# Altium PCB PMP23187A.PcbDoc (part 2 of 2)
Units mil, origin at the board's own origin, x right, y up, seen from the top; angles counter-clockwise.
Board outline 4000 x 3500 mil, 6 copper layers (Top Layer, Signal Layer 1, Signal Layer 2, Signal Layer 3, Signal Layer 4, Bottom Layer), stack 61.8 mil thick; 121 components, 42 nets, 273 pads, 535 vias.
Unrouted connection lines stored in the file: 23.
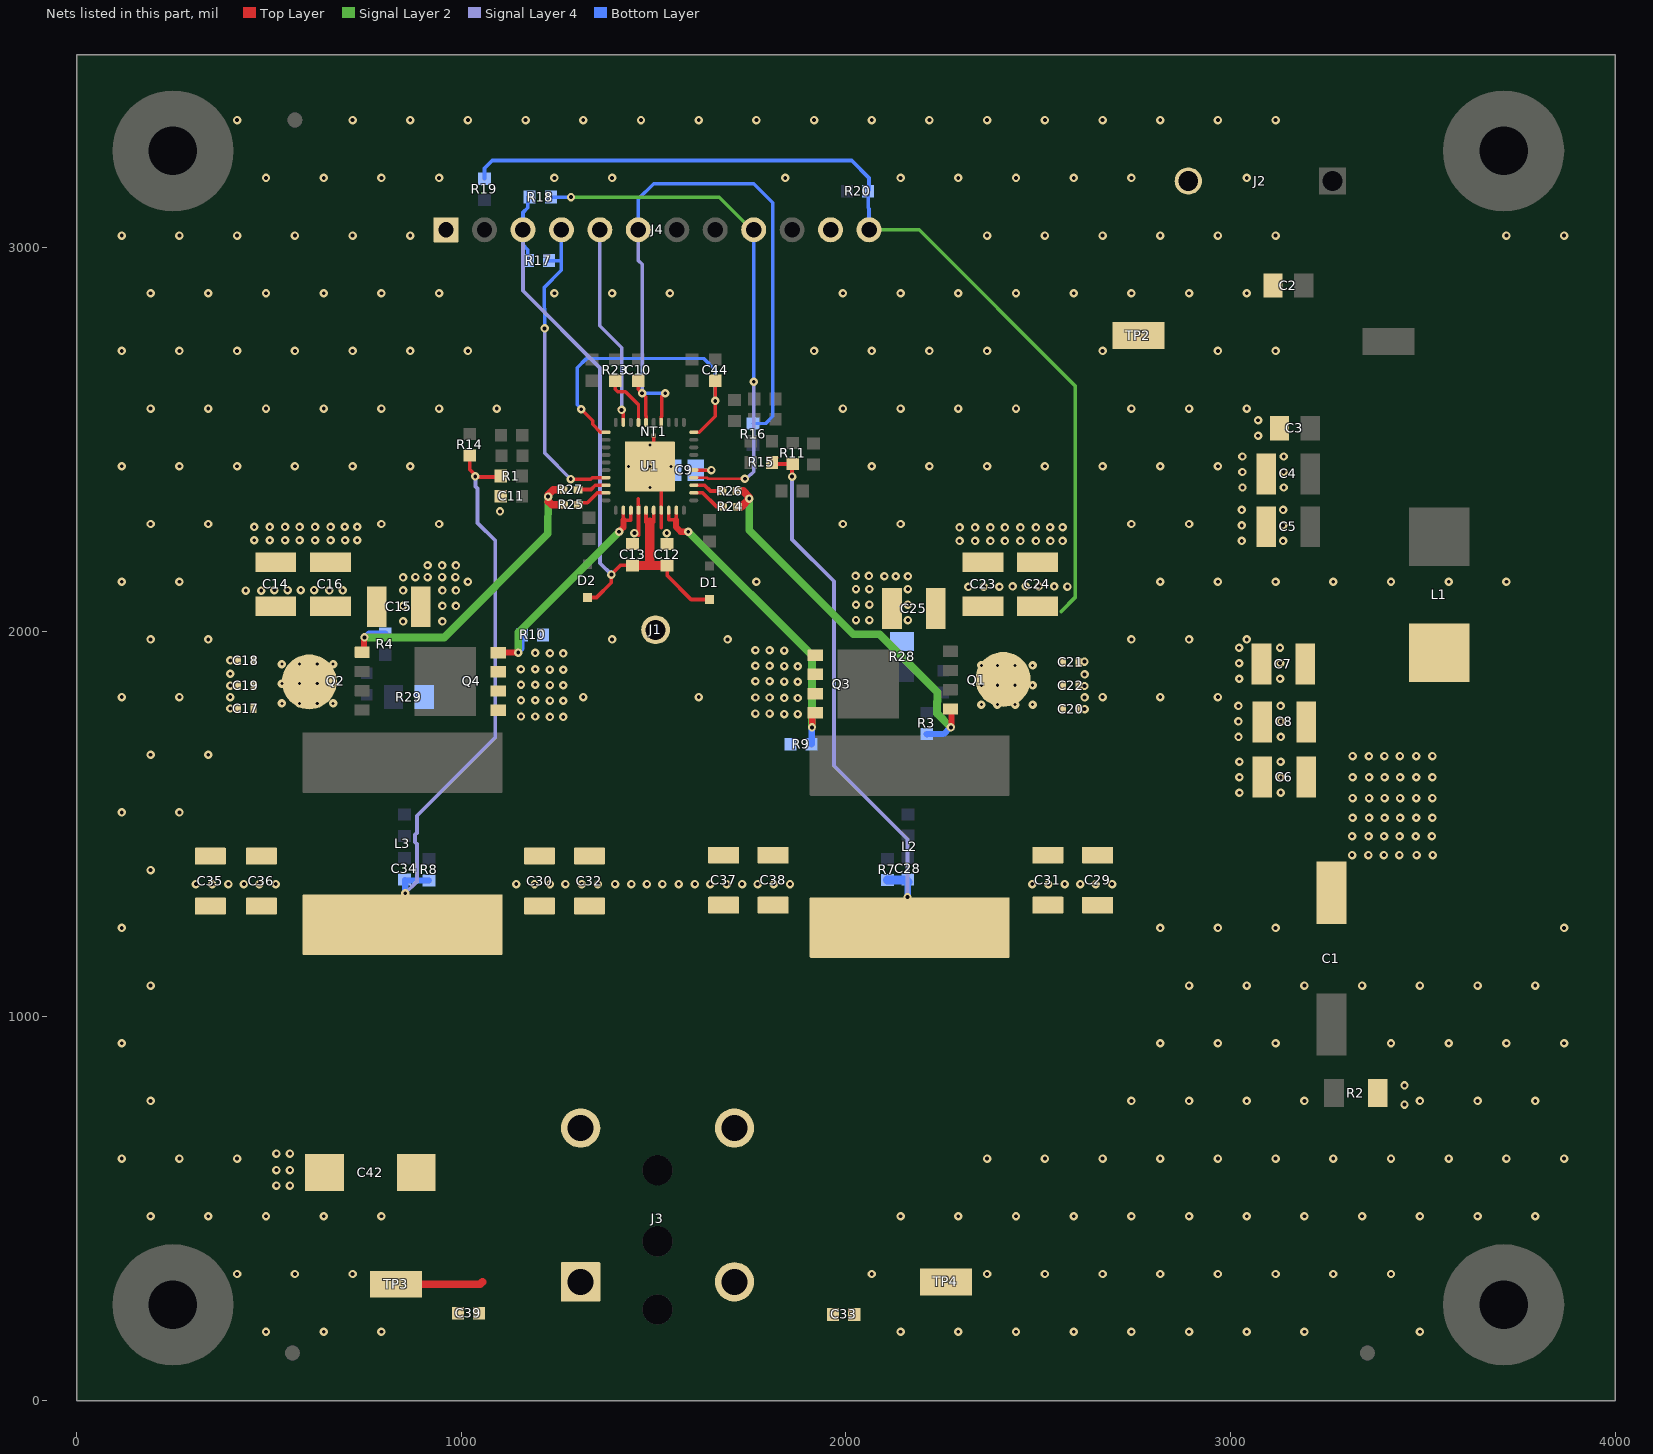
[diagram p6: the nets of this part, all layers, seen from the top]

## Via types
v1: diameter 22, hole 10, Top Layer to Bottom Layer, tented both sides, 504 vias
v2: diameter 22, hole 8, Top Layer to Bottom Layer, tented both sides, 24 vias
v3: diameter 19.68, hole 7.87, Top Layer to Bottom Layer, 5 vias
v4: diameter 24, hole 8, Top Layer to Bottom Layer, tented both sides, 2 vias

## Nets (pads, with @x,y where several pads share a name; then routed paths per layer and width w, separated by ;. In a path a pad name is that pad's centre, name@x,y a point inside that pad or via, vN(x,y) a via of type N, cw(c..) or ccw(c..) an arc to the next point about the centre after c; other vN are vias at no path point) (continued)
NetQ1_4: Q1.4 R3.1 R24.1 R26.1 | length 1041.5
  Top Layer w16: v1(2272.81,1751.28) 2274.09,1752.56 Q1.4@2274.09,1786.79
  Top Layer w20: R26.1@1716.79,2365.74 1732.54,2365.74 1748.39,2349.89 v1(1748.39,2345.9) 1748.39,2345.36 1728.44,2325.41 1718.28,2325.41 R24.1@1718.12,2325.25
  Signal Layer 2 w20: v1(1748.39,2345.9) 1748.39,2264.13 2019.34,1993.18 2087.07,1993.18 2237.87,1842.38 2237.87,1819.29 2236.57,1817.99 2236.57,1787.52 v1(2272.81,1751.28)
  Bottom Layer w16: R3.1@2210.53,1733.3 R3.1@2210,1733.83 2253.73,1733.83 2271.18,1751.28 v1(2272.81,1751.28) v1@2272.28,1750.75
NetQ2_4: Q2.4 R4.2 R25.2 R27.2 | length 878.4
  Top Layer w16: Q2.4@747.21,1940.12 v1@747.21,1983.92
  Top Layer w20: 1225.53,2338.19 1226.69,2338.19 1234.73,2330.16 R25.2@1265.31,2330.16 R25.2@1265.16,2330.31 ; v1@1226.01,2351.69 1226.01,2356.31 1238.93,2369.23 1263.75,2369.23 R27.2@1263.9,2369.38
  Signal Layer 2 w20: v1(748.1,1985) 955.5,1985 1224.86,2254.37 v1(1225.63,2351.31)
  Bottom Layer w16: v1(748.1,1985) 749.72,1985 759.76,1995.04 R4.2@801.97,1995.04
NetQ3_4: Q3.4 R9.1 U1.18 U1.19 | length 850.8
  Top Layer w9.5: U1.18@1539.21,2315.83 1539.21,2290.79 1558.11,2290.79 1558.9,2290 U1.19@1558.9,2315.83
  Top Layer w16: 1558.11,2290.79 1558.11,2271.89 1570,2260 v1(1590,2260) ; v1(1911.56,1751.28) 1912.09,1751.81 Q3.4@1912.09,1788.94
  Signal Layer 2 w20: v1(1590,2260) 1911.56,1938.44 v1(1911.56,1751.28)
  Bottom Layer w16: R9.1@1910.62,1707.2 1911.09,1707.67 1911.09,1750.81 v1(1911.56,1751.28)
NetQ4_4: Q4.4 R10.2 U1.12 U1.13 | length 622.3
  Top Layer w9.5: U1.12@1421.1,2315.83 1421.1,2290 1440,2290 1440.79,2290.79 U1.13@1440.79,2315.83
  Top Layer w16: Q4.4@1103.7,1945.63 1147.48,1945.63 v1(1147.67,1945.82) ; v1(1410,2260) 1421.1,2271.1 1421.1,2290
  Signal Layer 2 w20: v1(1147.67,1945.82) 1147.67,1997.67 v1(1410,2260)
  Bottom Layer w16: v1(1147.67,1945.82) 1147.67,1947.45 1156.15,1955.93 1156.15,1990.28 R10.2@1157.51,1991.64
NetR23_2: R23.2 U1.37 | length 145
  Top Layer w9: R23.2@1400,2652.44 1400,2630 1406.64,2623.36 1426.64,2623.36 1460.47,2589.53 U1.37@1460.47,2544.17
NetR24_2: R24.2 U1.22 | length 89.4
  Top Layer w9.8: U1.22@1604.17,2361.1 1627.15,2361.1 1663,2325.25 R24.2@1678.75,2325.25
NetR25_1: R25.1 U1.9 | length 84
  Top Layer w9.8: R25.1@1304.68,2330.16 1309.63,2335.1 1327.54,2335.1 1353.53,2361.09 U1.9@1375.83,2361.1
NetR26_2: R26.2 U1.23 | length 79.5
  Top Layer w9.8: U1.23@1604.17,2380.79 1632.46,2380.79 1647.5,2365.74 R26.2@1677.42,2365.74
NetR27_1: R27.1 U1.8 | length 83.6
  Top Layer w9.8: R27.1@1307.73,2364.93 R27.1@1303.27,2369.38 1336.83,2369.38 1348.23,2380.79 U1.8@1375.83,2380.79
PG1: J4.9 R18.1 U1.24 | length 1353.7
  Top Layer w7: U1.24@1604.17,2400.47 1604.17,2400 1638.36,2400 1640.73,2397.63 v1(1737.15,2397.63)
  Signal Layer 2 w9: v1(1285,3130) 1670,3130 J4.9@1760,3040
  Signal Layer 4 w9: v1(1737.15,2397.63) 1740.67,2397.63 1752.47,2409.42 1753.64,2409.42 1760,2415.79 v1(1760,2650)
  Bottom Layer w9: R18.1@1232.56,3130 v1(1285,3130) ; v1(1760,2650) J4.9@1760,3040
PG2: J4.4 R17.1 U1.7 | length 815.4
  Top Layer w9: v1(1284.53,2396.78) 1336.49,2396.78 1340.18,2400.47 U1.7@1375.83,2400.47
  Signal Layer 4 w9: v1(1216.17,2788.59) 1216.17,2465.15 v1(1284.53,2396.78)
  Bottom Layer w9: v1(1216.17,2788.59) 1215,2895 1260,2940 1260,2965 ; R17.1@1227.56,2965 1260,2965 ; J4.4@1260,3040 1260,2965
PGND: C2.1 C3.2 C4.2 C5.2 C6.2 C7.2 C8.2 C9.1 C11.2 C12.2 C13.2 C14.2 C15.2 C16.2 C17.2 C18.2 C19.2 C20.2 C21.2 C22.2 C23.2 C24.2 C25.2 C29.1 C30.1 C31.1 C32.1 C33.2 C35.1 C36.1 C37.1 C38.1 C39.2 C42.2 J1.1 J2.2 J3.2 J4.1 J4.11 NT1.2 Q3.1 Q3.2 Q3.3 Q4.1 Q4.2 Q4.3 R2.1 R9.2 R10.1 R28.1 R29.1 TP2.1 TP4.1 U1.14 U1.17 U1.41 | length 284.7
  Top Layer w9: U1.41@1499.84,2449.84 NT1.2@1499.84,2510
  Top Layer w9.5: 1460,2345 U1.14@1460.47,2315.83 1460.47,2250.47 ; 1519.53,2270.47 U1.17@1519.53,2315.83 U1.41@1519.53,2400.47
  other v1: 492,180 642,180 792,180 2142,180 2292,180 2442,180 2592,180 2742,180 2892,180 3042,180 3192,180 3492,180 417,330 567,330 717,330 2067,330 2367,330 2517,330 2667,330 2817,330 2967,330 3117,330 3267,330 3417,330 192,480 342,480 492,480 642,480 792,480 2142,480 2292,480 2442,480 2592,480 2742,480 2892,480 3042,480 3192,480 3342,480 3492,480 3642,480 3792,480 519.19,560 554.19,560 519.06,600.3 554.06,600.3 117,630 267,630 417,630 2367,630 2517,630 2667,630 2817,630 2967,630 3117,630 3267,630 3417,630 3567,630 3717,630 3867,630 519.19,642.88 554.19,642.88 3452.05,770.64 192,780 2742,780 2892,780 3042,780 3192,780 3492,780 3642,780 3792,780 3452.05,820.32 117,930 2817,930 2967,930 3117,930 3417,930 3567,930 3717,930 3867,930 192,1080 2892,1080 3042,1080 3192,1080 3342,1080 3492,1080 3642,1080 3792,1080 117,1230 2817,1230 2967,1230 3117,1230 3867,1230 309.74,1343.79 351.77,1343.79 394.09,1343.79 434.37,1343.79 474.67,1343.79 517.25,1343.79 1142.49,1343.79 1190.07,1343.66 1230.37,1343.79 1270.65,1343.79 1312.97,1343.79 1355,1343.79 1399.49,1343.79 1442.07,1343.66 1482.37,1343.79 1522.65,1343.79 1564.97,1343.79 1607,1343.79 1646.86,1343.79 1689.43,1343.79 1729.74,1343.79 1770.01,1343.79 1812.33,1343.79 1854.37,1343.79 2484.38,1343.79 2526.41,1343.79 2568.74,1343.79 2609.01,1343.79 2649.32,1343.79 2691.89,1343.79 192,1380 117,1530 267,1530 3022.78,1581.42 3130.22,1581.46 3022.65,1621.72 3130.22,1621.73 3022.65,1661.99 3130.09,1662.04 192,1680 342,1680 3020.52,1726.47 3130.22,1726.47 3020.39,1766.77 3130.22,1766.75 1230,1778.46 1265,1778.25 1155,1779.52 1192.03,1779.52 1839.45,1785.79 1874.45,1785.59 1764.45,1786.85 1801.48,1786.85 2620.31,1798.94 399.09,1800.28 3020.39,1807.05 3130.09,1807.05 1230,1820.78 1265,1820.58 1155,1821.84 1192.03,1821.84 1839.45,1827.82 1874.45,1827.62 1764.45,1828.89 1801.48,1828.89 2620.31,1829.19 117,1830 267,1830 399.09,1830 1317,1830 1617,1830 2667,1830 2817,1830 2967,1830 2620.11,1858.84 399.09,1859.77 1230,1861.06 1265,1860.85 1155,1862.12 1192.03,1862.12 1839.45,1870.14 1874.45,1869.94 1764.45,1871.21 1801.48,1871.21 3022.32,1877.57 3128.5,1877.57 2620.31,1888.94 399.09,1890.56 1229.87,1901.36 1264.87,1901.16 1154.87,1902.42 1191.9,1902.42 1839.45,1910.42 1874.45,1910.22 1764.45,1911.48 1801.48,1911.48 3022.19,1917.87 3128.5,1917.85 2620.11,1922.18 399.09,1925.22 1230,1943.93 1265,1943.73 1192.03,1945 1839.32,1950.72 1764.32,1951.79 1801.35,1951.79 3022.19,1958.15 3128.37,1958.15 192,1980 342,1980 1392,1980 1692,1980 2742,1980 2892,1980 3042,1980 848.46,2026.85 950.81,2026.85 2026.02,2030 2060.99,2030 2161.05,2030 848.33,2067.15 950.81,2066.92 985.79,2067.13 2026.02,2070.07 2060.99,2070.28 2160.92,2070.3 848.33,2107.43 950.81,2107.43 985.66,2107.43 2026.02,2110.58 2060.86,2110.58 2160.92,2110.58 117,2130 267,2130 1017,2130 1767,2130 2817,2130 2967,2130 3117,2130 3267,2130 3417,2130 3567,2130 3717,2130 848.46,2141.14 880.53,2141.85 912.14,2141.85 949.79,2141.85 984.52,2141.85 2100,2144.29 2129.34,2144.29 2161.05,2144.29 2025,2145 2059.72,2145 949.79,2172.44 985.79,2172.44 912.14,2172.57 2295.44,2236.1 2335.48,2236.1 2375.44,2236.1 2413.09,2236.1 2453.39,2236.1 2493.67,2236.1 2531.46,2236.1 2562.96,2236.1 3029.07,2236.06 3136.51,2236.1 461.56,2237.59 501.6,2237.59 541.56,2237.59 579.21,2237.59 619.51,2237.59 659.79,2237.59 697.58,2237.59 729.08,2237.59 1450,2256.24 1533.76,2256.24 2295.44,2270.99 2335.48,2270.99 2375.44,2270.99 2413.09,2270.99 2453.39,2270.99 2493.67,2270.99 2530.48,2271.48 2562.96,2271.48 461.56,2272.47 501.6,2272.47 541.56,2272.47 579.21,2272.47 619.51,2272.47 659.79,2272.47 696.6,2272.97 729.08,2272.97 3028.94,2276.36 3136.51,2276.38 192,2280 342,2280 792,2280 942,2280 1992,2280 2142,2280 2742,2280 2892,2280 1100.45,2312.87 3028.94,2316.64 3136.38,2316.68 3030.87,2374.89 3138.31,2374.93 3030.74,2415.19 3138.31,2415.21 117,2430 267,2430 417,2430 567,2430 717,2430 867,2430 2067,2430 2217,2430 2367,2430 2517,2430 2667,2430 2817,2430 2967,2430 3030.74,2455.47 3138.18,2455.51 3071.38,2509.51 3071.38,2549.78 192,2580 342,2580 492,2580 642,2580 792,2580 942,2580 1092,2580 1992,2580 2142,2580 2292,2580 2442,2580 2742,2580 2892,2580 3042,2580 117,2730 267,2730 417,2730 567,2730 717,2730 867,2730 1017,2730 1917,2730 2067,2730 2217,2730 2367,2730 2667,2730 2967,2730 3117,2730 192,2880 342,2880 492,2880 642,2880 792,2880 942,2880 1242,2880 1392,2880 1542,2880 1992,2880 2142,2880 2292,2880 2442,2880 2592,2880 2742,2880 2892,2880 3042,2880 117,3030 267,3030 417,3030 567,3030 717,3030 867,3030 2367,3030 2517,3030 2667,3030 2817,3030 2967,3030 3117,3030 3717,3030 3867,3030 492,3180 642,3180 792,3180 942,3180 1242,3180 1392,3180 1842,3180 2142,3180 2292,3180 2442,3180 2592,3180 2742,3180 3042,3180 417,3330 717,3330 867,3330 1017,3330 1167,3330 1317,3330 1467,3330 1617,3330 1767,3330 1917,3330 2067,3330 2217,3330 2367,3330 2517,3330 2667,3330 2817,3330 2967,3330 3117,3330
  other v3: 1490,2374.88 1434.88,2430 1490,2430 1545.12,2430 1490,2485.12
SS: C44.1 U1.1 U1.30 | length 834.2
  Top Layer w9: v1(1311.63,2578.37) 1341.06,2548.94 1341.06,2538.94 1361.42,2518.58 U1.1@1375.83,2518.58 ; U1.30@1604.17,2518.58 1618.58,2518.58 1660,2560 v1(1660,2600) C44.1@1660,2652.44
  Bottom Layer w9: v1(1311.63,2578.37) 1311.63,2579.36 1300.84,2590.15 1300.84,2685.84 1325.32,2710.31 1611.14,2710.31 1629.89,2710.31 1660,2680.2 v1(1660,2600)
SYNCOUT: J4.5 U1.39 | length 530.2
  Top Layer w9: v1@1410,2580 v1@1413.37,2576.63 ; v1(1416.43,2576.63) v1@1413.37,2576.63 ; U1.39@1421.1,2544.17 1421.1,2568.9 v1@1413.37,2576.63
  Signal Layer 4 w9: J4.5@1360,3040 1360,2795 1416.43,2738.57 v1(1416.43,2576.63)
VCC: C12.1 C13.1 D1.2 D2.2 J4.3 R17.2 R18.2 U1.15 U1.16 | length 1789.1
  Top Layer w9.5: D2.2@1327.71,2088.77 1351.59,2088.77 1390,2127.18 v1(1390,2148.59) 1413.85,2172.44 C13.1@1445,2172.44 C13.1@1450,2172.44 ; U1.15@1480.16,2315.83 1480.16,2285 1490,2285 1499.84,2285 U1.16@1499.84,2315.83 ; C12.1@1535,2172.44 1535,2146.11 1597.24,2083.87 D1.2@1645.22,2083.87 D1.2@1638.15,2090.93
  Top Layer w24: C13.1@1450,2172.44 C12.1@1535,2172.44 ; 1490,2175 1490,2285
  Signal Layer 4 w10: J4.3@1160,3039 1160,2886.34 1360.75,2685.59 1360.75,2177.84 v1(1390,2148.59)
  Bottom Layer w9.5: R17.2@1172.44,2965 1172.44,2993.35 1160,3005.79 J4.3@1160,3045 1160,3090 1172.44,3102.44 R18.2@1172.44,3130 ; v1@1387.5,2152.5 1390,2155 v1(1390,2148.59)
VDDA: C10.2 J4.6 R16.2 U1.34 U1.36 | length 1762.7
  Top Layer w9: C10.2@1460,2652.44 1460,2630 v1(1470,2620) 1479.63,2610.37 1479.63,2578.6 1479.47,2578.44 1479.47,2561.4 1480.16,2560.71 U1.36@1480.16,2544.17 ; U1.34@1519.53,2544.17 1519.53,2559.53 1520.37,2560.37 1520.37,2610.37 v1(1530,2620)
  Signal Layer 4 w9: J4.6@1460,3040 1460,2965 1470,2955 v1(1470,2620)
  Bottom Layer w9: J4.6@1460,3045 1460,3125 1500,3165 1760,3165 1810,3115 1810,2560 1791.26,2541.26 R16.2@1758.35,2541.26 ; v1(1470,2620) v1(1530,2620)
VIN: C1.1 C6.1 C7.1 C8.1 C9.2 C14.1 C15.1 C16.1 C17.1 C18.1 C19.1 C20.1 C21.1 C22.1 C23.1 C24.1 C25.1 J4.12 L1.2 Q1.5-6 Q2.5-6 R19.2 R20.2 U1.25 | length 2583.5
  Top Layer w9.5: U1.25@1604.17,2420.16 1649.84,2420.16 v1(1650,2420)
  Signal Layer 2 w9.5: J4.12@2060,3045 2190.31,3045 2595.61,2639.7 2595.61,2088.65 2559.32,2052.36
  Bottom Layer w9.5: R19.2@1060,3177.56 1060,3205 1080,3225 2014.78,3225 2060,3179.78 2060,3147.44 R20.2@2057.56,3145 2057.56,3102.44 2060,3100 J4.12@2060,3045 ; C9.2@1609.53,2420 v1(1650,2420)
  other v1: 3315.87,1419.11 3358.44,1418.98 3398.74,1419.11 3439.02,1419.11 3483.68,1418.98 3525.71,1418.98 3316.01,1468.19 3358.59,1468.06 3398.89,1468.19 3439.16,1468.19 3481.49,1468.19 3523.52,1468.19 3317.32,1516.41 3359.9,1516.28 3400.2,1516.41 3440.48,1516.41 3482.8,1516.41 3524.83,1516.41 3317.32,1567.38 3359.9,1567.25 3400.2,1567.38 3440.48,1567.38 3482.8,1567.38 3524.83,1567.38 3317.32,1621.73 3359.9,1621.6 3400.2,1621.73 3440.48,1621.73 3482.8,1621.73 3524.83,1621.73 3317.12,1676.41 3359.7,1676.28 3400,1676.41 3440.28,1676.41 3482.6,1676.41 3524.63,1676.41 439.28,2106.69 479.58,2106.82 656.73,2107.43 691.46,2107.43 513.82,2108.07 548.27,2108.07 582.37,2108.07 617.1,2108.07 2318.22,2116.54 2358.5,2116.54 2398.8,2116.67 2575.52,2117.35 2433.03,2117.92 2467.48,2117.92 2501.59,2117.92 2541.41,2117.92
  other v2: 2352.06,1810.43 2393.49,1810.43 2439.65,1810.43 2485.22,1810.43 533.43,1813.48 579,1813.48 625.16,1813.48 666.59,1813.48 2352.06,1860.83 2393.49,1860.83 2439.65,1860.83 2485.22,1860.83 533.43,1865.12 579,1865.12 625.16,1865.12 666.59,1865.12 2352.06,1912.47 2393.49,1912.47 2439.65,1912.47 2485.22,1912.47 533.43,1915.51 579,1915.51 625.16,1915.51 666.59,1915.51
VOUT: C28.2 C29.2 C30.2 C31.2 C32.2 C33.1 C34.2 C35.2 C36.2 C37.2 C38.2 C39.1 C42.1 J3.1 L2.1 L3.2 R1.2 R7.2 R8.1 R11.2 R14.2 R15.2 TP3.1 | length 3173
  Top Layer w9: R15.2@1807.56,2440 1807.56,2440.98 1818.81,2452.23 R15.2@1819.79,2452.23
  Top Layer w10: R14.2@1021.61,2458.58 1021.61,2421.69 1036.13,2407.17 v1(1036.13,2403.93) 1039.33,2403.93 1040.82,2402.44 1100.45,2402.44 R1.2@1102.44,2404.43 ; R15.2@1807.56,2440 1811.68,2435.88 R11.2@1861.65,2435.88 1860,2434.23 v1(1860,2403.2) ; v1(2159.93,1310) L2.1@2160.55,1215.91
  Top Layer w20: TP3.1@830,303.42 1048.97,303.42 1055,309.45
  Signal Layer 4 w10: v1(853.9,1320) 884.37,1350.47 884.37,1447.93 879.83,1452.47 879.83,1472.25 884.37,1476.79 884.37,1521.53 1088.06,1725.22 1088.06,2236.67 1042.13,2282.6 1042.13,2372.65 1036.85,2377.93 1036.85,2403.2 v1(1036.13,2403.93) ; v1(1860,2403.2) 1860,2240 1968.89,2131.11 1968.89,1651.3 2159.93,1460.26 v1(2159.93,1310)
  Bottom Layer w10: C34.2@851.99,1355.92 853.9,1354 C34.2@854.79,1353.12 ; v1@2156.99,1312.3 v1@2160.55,1315.86
  Bottom Layer w16: v1(853.9,1320) C34.2@853.9,1354 ; C34.2@854.79,1353.12 R8.1@915.95,1353.12 ; v1@2160.55,1315.86 C28.2@2160.55,1349.03
  Bottom Layer w24: R7.2@2107.69,1354.1 2155.47,1354.1 C28.2@2160.55,1349.03
pads on no net: FID1.1 FID2.1 FID3.1 FID4.1 FID5.1 FID6.1 H1.1 H2.1 H3.1 H4.1 H5.0 H6.0 H7.0 H8.0 J3. U1.0

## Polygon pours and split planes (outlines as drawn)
NetC26_1 on Top Layer "TOP_LAYER_NETC26_1_P1144" (solid, remove dead copper, pour order 1144): 2263.44,1603 1978.59,1603 1978.59,1952.72 1979.66,1951.64 2302.65,1951.64 2302.65,1811.59 2237.42,1811.59 2228,1802.17 2228,1749.75 2244.18,1733.56 2263.44,1733.56
NetC27_1 on Top Layer "TOP_LAYER_NETC27_1_P1145" (solid, remove dead copper, pour order 1145): 716.69,1911.48 805.35,1911.48 831.32,1937.46 831.32,2000.48 1038.83,2000.48 1038.83,1609.71 716.69,1609.71
AGND on Top Layer "TOP_LAYER_AGND_P1146" (solid, remove dead copper, pour order 1146): 1800,2475.53 1920,2475.53 1920,2695.53 1770,2845.53 1311.51,2845.53 1185.07,2719.09 1185.07,2460 1290,2460 1290,2667.35 1318.18,2695.53 1710,2695.53 1800,2605.53
VIN on Top Layer "TOP_LAYER_VIN_P1147" (solid, remove dead copper, pour order 1147): 2649.32,1651.94 2649.32,1767.32 2584.45,1767.32 2584.45,1951.2 2649.32,1951.2 2649.32,2139.01 2210,2139.01 2210,1970.24 2312.13,1970.24 2325.55,1956.82 2325.55,1651.94
VIN on Top Layer "TOP_LAYER_VIN_P1148" (solid, remove dead copper, pour order 1148): 374.01,1648 374.01,1765.63 439.28,1765.63 439.28,1963.98 374.01,1963.98 374.01,2133.11 814.04,2133.11 814.04,1955.63 707.26,1955.63 707.26,1648
VOUT on Top Layer "TOP_LAYER_VOUT_P1149" (solid, remove dead copper, pour order 1149): 1028.52,332.06 777,583.58 591.97,768.61 339.01,768.61 254.06,853.56 254.06,1315.85 587.19,1315.86 2424.51,1315.86 2750.24,1315.86 2750.24,853.99 2664.86,768.61 2396.22,768.61 2211.19,583.58 1983.58,355.97 1983.58,28.2 1028.52,28.2
PGND on Top Layer "TOP_LAYER_PGND_P1150" (solid, pour order 1150): 0,0 0,3505 4000,3505 4000,0
VIN on Signal Layer 2 "SIGNAL_LAYER_2_VIN_P1152" (solid, remove dead copper, pour order 1152): 420.62,2130.65 420.62,1513.95 559.28,1375.29 3660,1366.46 3660,1700 2646.88,1700 2599.31,1747.57 2599.31,2144.42 2302.65,2144.42 2302.65,1757.56 2279.74,1734.19 2265.44,1733.9 1632.39,1733.9 1588.69,1777.6 1588.69,2258.59 1664.01,2333.9 1664.01,2442.28 1621.91,2442.28 1617.78,2438.14 1617.78,2377.02 1555.49,2314.73 1452.32,2314.73 1429.01,2291.42 1429.01,2249.38 1429.01,1773.9 1364.06,1708.95 748.96,1708.95 707.26,1750.65 707.26,2130.65
PGND on Signal Layer 2 "Top Layer-No Net2" (solid, pour order 1153): 4.6,0 4.6,3508.05 4000,3508.05 4000,0
VOUT on Bottom Layer "BOTTOM_LAYER_VOUT_P1156" (solid, remove dead copper, pour order 1156): 1260.2,285 1110,285 1100.2,275.2 1009.8,275.2 1000,285 829.8,285 820,275.2 820,70 840,50 1250,50 1270,70 1270,275.2
no net on Bottom Layer "BOTTOM_LAYER_NONET_P1157" (solid, remove dead copper, pour order 1157): 2825,2505 2825,2155 2835,2145 3100,2145 3110,2155 3110,2275 3119.69,2284.69 3119.69,2505
no net on Bottom Layer "BOTTOM_LAYER_NONET_P1158" (solid, remove dead copper, pour order 1158): 3810,1475 3810,1225 3794.89,1209.89 3420.11,1209.89 3403.31,1226.69 3403.31,1383.31 3420,1400 3475,1400 3515,1440 3515,1480 3530,1495 3790,1495
no net on Bottom Layer "BOTTOM_LAYER_NONET_P1159" (solid, remove dead copper, pour order 1159): 3200,2030 3580,2030 3590,2020 3590,1665 3580,1655 3410,1655 3400,1665 3400,1865 3200,1865 3190,1875 3190,2020
VOUT on Bottom Layer "BOTTOM_LAYER_VOUT_P1160" (solid, remove dead copper, pour order 1160): 2165,290 2325,290 2339.78,275.22 2415.22,275.22 2430,290 2590,290 2610,270 2610,75 2590,55 2160,55 2140.18,74.82 2140.18,265.18
no net on Bottom Layer "BOTTOM_LAYER_NONET_P1161" (solid, remove dead copper, pour order 1161): 3153.86,2505 3525,2505 3525,2155 3515,2145 3235,2145 3225,2155 3225,2190 3153.86,2190 3153.86,2346.14
no net on Bottom Layer "BOTTOM_LAYER_NONET_P1162" (solid, remove dead copper, pour order 1162): 2835.01,2030 3150,2030 3160,2020 3160,1824.8 3169.8,1815 3300,1815 3310,1805 3310,1665 3300,1655 3000,1655 2820,1835 2820.49,2015.52
VIN on Bottom Layer "BOTTOM_LAYER_VIN_P1163" (solid, remove dead copper, pour order 1163): 2602.58,1657.88 2602.58,2150.36 2208.13,2150.36 2208.13,1976.18 2325.55,1976.18 2336.96,1964.77 2336.96,1657.88
VIN on Bottom Layer "BOTTOM_LAYER_VIN_P1164" (solid, remove dead copper, pour order 1164): 417.12,1648 417.12,2133.11 814.04,2133.11 814.04,1955.63 695.2,1955.63 695.2,1648
PGND on Bottom Layer "Top Layer-No Net3" (solid, pour order 1165): 0,0 0,3505 4000,3505 4000,0
PGND on Signal Layer 4 "Top Layer-No Net2" (solid, pour order 1155): 0,0 0,3505 4000,3505 4000,0
PGND on Signal Layer 3 "Top Layer-No Net4" (solid, pour order 1154): 0,0 0,3505 4000,3505 4000,0
PGND on Signal Layer 1 "Top Layer-No Net1" (solid, pour order 1151): 0,0 0,3505 4000,3505 4000,0

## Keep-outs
Keep-Out Layer:
  the board outline again, w10
  text ".Layer_Name" at 111,-1094.49 h60

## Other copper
Top Layer:
  pour cut-out: 3165.46,2150.55 3165.46,2042.37 3168.41,2039.42 3877.32,2039.42 3877.32,2141.22 3868,2150.55
  region net VIN: 3170,2030 3873.42,2030 3873.42,1273.42 3800,1200 3174.58,1200
  region net PGND: 3000,3400 3000,2753.83 3138.23,2753.83 3138.23,2339.01 3018.7,2339.01 2619.59,2339.01 2619.59,3400
  region net NetC2_2: 3868,2160.75 3868,2970 3685.38,2964.23 3477.85,3165.3 3477.85,3450 3299.02,3450 3165.46,3450 3165.46,2160.74
  text ".Layer_Name" at 111,-1094.49 h60
Signal Layer 1:
  text "'.Layer_Name'" at 109,-1096 h60
Signal Layer 2:
  text "'.Layer_Name'" at 109,-1096 h60
Signal Layer 3:
  text "'.Layer_Name'" at 114,-1096 h60
Signal Layer 4:
  text "'.Layer_Name'" at 109,-1096 h60
Bottom Layer:
  text ".Layer_Name" at 111,-1094.49 h60

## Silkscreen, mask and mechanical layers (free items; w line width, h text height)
Top Overlay:
  text "VIN:" at 2340,3323.25 h100
  text "48VDC" at 2298.91,3225 h85
  text "(65VDC Max)" at 2250,3157.8 h65
  text "PGND" at 980,3125 h40 r90
  text "EN2" at 1075,3125 h40 r90
  text "EN1" at 1885,3125 h40 r90
  text "VIN" at 2090,3125 h40 r90
  text "VCC" at 1180,3120 h40 r90
  text "PG2" at 1285.45,3120.45 h40 r90
  text "SYNCOUT" at 1380,3120 h40 r90
  text "VDDA" at 1460,3120 h40 r90
  text "AGND" at 1695,3120 h40 r90
  text "PG1" at 1780,3120 h40 r90
  text "PGND" at 1985,3120 h40 r90
  text "DEMB- / SYNCIN" at 1651.81,3023.25 h40 r90
  text "-" at 2481.96,2990.26 h200
  text "+" at 3542.16,2950 h200
  text "GND" at 1435,1825 h40
  text "CAUTION: / HOT SURFACE" at 1219.88,1391.76 h40
  text "VOUT = 5VDC @ 50A MAX" at 1141.61,847 h40
  text "LM5143Q-2PH" at 2662.07,397.29 h60
  text "'.PRJ_Number'.PCB_Rev" at 2785.27,262.59 h60
  text "VOUT-" at 2182,198.29 h40
  text "VOUT+" at 743.55,172.6 h40
  text "-" at 2021.58,97.27 h200
  text "+" at 952.16,80 h200
  text ".Layer_Name" at 111,-1094.49 h60
Bottom Overlay:
  text ".Layer_Name" at 111,-1094.49 h60
Top Paste:
  text ".Layer_Name" at 111,-1094.49 h60
Bottom Paste:
  text ".Layer_Name" at 111,-1094.49 h60
Top Solder:
  text ".Layer_Name" at 111,-1094.49 h60
  text ".Layer_Name" at 111,-1094.49 h60
Bottom Solder:
  text ".Layer_Name" at 111,-1094.49 h60
Drill Guide:
  text ".Layer_Name" at 111,-1094.49 h60
M1 Board Outline:
  the board outline again, w10
  text ".Layer_Name" at 111,-1094.49 h60
M2 Board Dimensions:
  rectangle: -466,-511 -341,-386
  rectangle: -341,-636 34,-511
  lines w7: -466,-511 534,-511 ; -341,-636 -341,-386 ; -216,-636 -216,-386 ; 34,-636 34,-386 ; 284,-636 284,-386 ; -466,-636 534,-636 534,-386 -466,-386 -466,-636
  text ".Layer_Name" at 111,-1094.49 h60
M3 3D STEP Top:
  text ".Layer_Name" at 111,-1094.49 h60
M4 3D STEP Bottom:
  text ".Layer_Name" at 111,-1094.49 h60
M5 Assembly Top:
  circle w3.94: c867.95,900.24 r8.8
  lines w10: -758,-1166.17 5842,-1166.17 ; -758,-962.83 5844,-962.83 ; -758,-759.5 -758,-1369.5 3247,-1369.5 5844,-1369.5 5844,-759.5 -757.5,-759.5 -757.5,-1369.5 818,-1369.5 ; 1707,-1369.5 1707,-759.5 ; 2974,-962.83 2974,-759.5 ; 3814,-962.83 3814,-759.5 ; 4436,-1376 4436,-1173.17
  text "COMPONENTS MARKED 'DNP' SHOULD NOT BE POPULATED." at 687.5,-554.5 h60
  text "ASSEMBLY VARIANT:" at 687,-670 h60
  text ".VariantName" at 1723,-670 h60
  text "PCB VIEWED FROM TOP SIDE" at -694.5,-891.67 h60
  text "BOARD #:" at 1782,-891.67 h60
  text ".PRJ_Number" at 2327.5,-891.67 h60
  text "REV:" at 3172,-891.67 h60
  text ".PCB_Rev" at 3463.5,-891.67 h60
  text "SVN REV:" at 4010,-891.67 h60
  text ".VersionControl_RevNumber" at 4516,-891.67 h60
  text "TID #:" at 1782,-1095 h60
  text ".TID" at 2327.5,-1095 h60
  text "PLOT NAME =" at -694.5,-1300.34 h60
  text ".plot_File_Name" at 111,-1300.34 h60
  text "GENERATED    :" at 1784,-1300.34 h60
  text ".Print_Date" at 2653.5,-1300.34 h60
  text ".Print_Time" at 3382.5,-1300.34 h60
  text "TEXAS INSTRUMENTS" at 4647,-1300.34 h60
M6 Assembly Bottom:
  lines w10: -758.5,-963.33 5843.5,-963.33 ; -756.5,-1166.67 5843.5,-1166.67 ; 649.5,-1376.5 649.5,-1173.67 ; 1271.5,-963.33 1271.5,-760 ; 2111.5,-963.33 2111.5,-760 ; 3378.5,-1370 3378.5,-760 ; 4267.5,-1370 5843,-1370 5843,-760 -758.5,-760 -758.5,-1370 1838.5,-1370 5843.5,-1370 5843.5,-760
  text "COMPONENTS MARKED 'DNP' SHOULD NOT BE POPULATED." at 5636,-554 h60
  text ".VariantName" at 4592,-670 h60
  text "ASSEMBLY VARIANT:" at 5631,-670 h60
  text ".VersionControl_RevNumber" at 569.5,-892.17 h60
  text "SVN REV:" at 1075.5,-892.17 h60
  text ".PCB_Rev" at 1622,-892.17 h60
  text "REV:" at 1913.5,-892.17 h60
  text ".PRJ_Number" at 2758,-892.17 h60
  text "BOARD #:" at 3303.5,-892.17 h60
  text "PCB VIEWED FROM BOTTOM SIDE" at 5780,-892.17 h60
  text ".TID" at 2758,-1095.5 h60
  text "TID #:" at 3303.5,-1095.5 h60
  text "TEXAS INSTRUMENTS" at 438.5,-1300.84 h60
  text ".Print_Time" at 1703,-1300.84 h60
  text ".Print_Date" at 2432,-1300.84 h60
  text "GENERATED    :" at 3301.5,-1300.84 h60
  text ".plot_File_Name" at 4974.5,-1300.84 h60
  text "PLOT NAME =" at 5780,-1300.84 h60
M9 Title Sheet:
  drawing of 57 lines, arcs and shapes, not listed
  text "1" at 273.84,7800.5 h70
  text "2" at 2769.5,7800.5 h70
  text "3" at 5258.84,7800.5 h70
  text "4" at 7765.51,7800.5 h70
  text "5" at 10264.5,7800.5 h70
  text "6" at 12769.5,7800.5 h70
  text "A" at -882.5,6657.5 h70
  text "A" at 13917.5,6657.5 h70
  text "B" at -882.5,4277.5 h70
  text "B" at 13917.5,4277.5 h70
  text "C" at -882.5,1902.5 h70
  text "C" at 13917.5,1902.5 h70
  text "PROJECT TITLE:" at 10877.5,41.5 h45
  text ".PRJ_Title" at 10927.5,-91.83 h70
  text "DESIGNED FOR:" at 10877.5,-259.5 h45
  text ".PRJ_Customer" at 10927.5,-399.5 h70
  text "D" at -882.5,-467.5 h70
  text "D" at 13917.5,-467.5 h70
  text "FILE NAME:" at 10877.5,-559.5 h45
  text ".PCB_File_Name_No_Path" at 10927.5,-679.5 h70
  text "Texas Instruments (TI) and/or its licensors do not warrant the accuracy or completeness of this specification" at 5908,-841.34 h45
  text "ENGINEER:" at 10877.5,-849.5 h45
  text "LAYOUT BY:" at 12382.5,-849.5 h45
  text "or any information contained therein. TI and/or its licensors do not warrant that this design will meet" at 5863.01,-954 h45
  text ".PRJ_Engineer" at 10927.5,-1004.49 h70
  text ".PCB_Layout" at 12433,-1004.49 h70
  text "the specifications, will be suitable for your application or fit for any particular purpose, or will operate in" at 5863.01,-1066.67 h45
  text ".Layer_Name" at 111,-1094.49 h60
  text "ALTIUM DESIGNER VERSION:" at 12382.5,-1159.5 h45
  text "an implementation. TI and/or its licensors do not warrant that the design is production worthy. You should" at 5863.01,-1179.33 h45
  text "completely validate and test your design implementation to confirm the system functionality for your application." at 5908,-1292 h45
  text ".print_Scale" at 10927.5,-1292.83 h70
  text ".Application_BuildNumber" at 12433,-1292.83 h70
  text "1" at 273.84,-1499.5 h70
  text "2" at 2769.5,-1499.5 h70
  text "3" at 5258.84,-1499.5 h70
  text "4" at 7765.51,-1499.5 h70
  text "5" at 10264.5,-1499.5 h70
  text "6" at 12769.5,-1499.5 h70
M10 Fab Notes:
  drawing of 189 lines, arcs and shapes, not listed
  text "DESIGN INFORMATION" at 11916.02,6120.17 h60
  text "MIN. TRACK WIDTH:" at 11271.46,5988.05 h60
  text "7" at 12367.7,5988.05 h60
  text "MIL" at 12522.46,5988.05 h60
  text "MIN. CLEARANCE:" at 11271.46,5863.92 h60
  text "0.2" at 12307.7,5863.93 h60
  text "mm" at 12522.46,5863.92 h60
  text "MIN. VIA PAD SIZE:" at 11271.46,5739.8 h60
  text "19.685" at 12130,5739.8 h60
  text "MIL" at 12522.46,5739.8 h60
  text "0.05mm (2MIL)" at 11966.46,5609.9 h60
  text "MINIMUM ANNULAR RING" at 10942.23,5601.67 h60
  text "EXTERNAL" at 12674.46,5601.67 h60
  text "PER" at 11142.23,5491.55 h60
  text "IPC-D-275 CLASS 2 LEVEL C" at 11362.23,5491.54 h60
  text "MIL, HOLES" at 12850.46,5391.07 h60
  text "+/-" at 12458,5382.48 h60
  text "+/-" at 13312,5382.48 h60
  text "REGISTRATION TOLERANCES:" at 10942.23,5381.42 h60
  text "METAL" at 12142,5381.42 h60
  text "5" at 12718.2,5381.42 h60
  text "3" at 13551.2,5381.42 h60
  text "MIL" at 13667.46,5381.42 h60
  text "HOLE SIZE TOLERANCE (UNLESS OTHERWISE SPECIFIED):" at 10942.23,5283.1 h60
  text "+/-" at 13312,5280.23 h60
  text "3" at 13551.2,5279.17 h60
  text "MIL" at 13667.46,5279.17 h60
  text "MATERIAL:" at 10867.46,5141.52 h60
  text "FR-4 High Tg" at 11853.9,5013 h60
  text "X" at 11709.46,5005.01 h60
  text "FR-408" at 11288.46,5000.49 h60
  text "OTHER" at 12776.46,5000.49 h60
  text "62 MIL (1.6mm) +/-10%" at 11608.56,4857.46 h60
  text "X" at 11488.46,4855.01 h60
  text "THICKNESS:" at 10942.23,4849.24 h60
  text "OTHER" at 12893.46,4849.24 h60
  text "TOLERANCE:" at 10942.23,4710.92 h60
  text "X" at 11790.46,4710.92 h60
  text "ANSI IPC-6012 TYPE 3 CLASS 2" at 11968.48,4710.92 h60
  text "OTHER +/-" at 11968.46,4566.73 h60
  text "BOW & TWIST:" at 10942.23,4421.54 h60
  text "X" at 11790.46,4421.54 h60
  text "ANSI IPC-6012 TYPE 3 CLASS 2" at 11968.48,4421.54 h60
  text "OTHER +/-" at 11968.46,4274.85 h60
  text "DRILLING:" at 10867.46,4144.23 h60
  text "NC_DRILL FILES" at 12628.46,4039.04 h60
  text "REFERENCE:" at 10942.23,4035.1 h60
  text "X" at 11599.46,4035.01 h60
  text "AS SHOWN" at 11777.46,4035.1 h60
  text "X" at 12500.46,4035.1 h60
  text "OTHER" at 12926.46,3892.85 h60
  text "PTH COPPER THICKNESS:" at 10941.91,3889.32 h60
  text "X" at 12081.14,3889.32 h60
  text "20-30 um" at 12209.14,3889.32 h60
  text "BOARD FINISH:" at 10867.46,3741.73 h60
  text "SILKSCREEN:" at 11022.68,3631.6 h60
  text "X" at 11980.46,3631.6 h60
  text "TOP" at 12097.46,3631.6 h60
  text "X" at 12490.46,3631.6 h60
  text "BOTTOM" at 12608.46,3631.6 h60
  text "SILKSCREEN COLOR:" at 11022.68,3476.41 h60
  text "X" at 11979.46,3476.41 h60
  text "WHITE" at 12097.46,3476.41 h60
  text "OTHER" at 12608.46,3476.41 h60
  text "X" at 12110.46,3332.96 h60
  text "GREEN" at 12228.46,3332.96 h60
  text "OTHER" at 12846.46,3332.96 h60
  text "SOLDER RESIST COLOR:" at 11022.68,3326.1 h60
  text "X" at 12110.46,3178.71 h60
  text "MATTE" at 12228.46,3178.71 h60
  text "SEMI-GLOSS" at 12846,3178.07 h60
  text "IMMERSION GOLD (ENIG)" at 11928.46,3005.94 h60
  text "ENEPIG" at 13266,2998.72 h60
  text "SURFACE FINISH:" at 10867.46,2997.72 h60
  text "X" at 11750.46,2997.72 h60
  text "IMM. TIN/SILVER OR EQUIV" at 11197,2860.4 h60
  text "OTHER" at 12628.46,2856.47 h60
  text "ARRAY/PANEL:" at 10867.46,2701.09 h60
  text "CUT AND TRIM PER M1 BOARD OUTLINE" at 11928.46,2692.87 h60
  text "N.C. ROUTE" at 11928.46,2556.9 h60
  text "X" at 12616.46,2556.9 h60
  text "V. SCORE" at 12794.46,2556.9 h60
  text "CERTIFICATION:" at 10867.46,2427.77 h60
  text "MATERIALS AND WORKMANSHIP FOR ALL PCBS" at 11592.46,2427.77 h60
  text "TO MEET OR EXCEED THE REQUIREMENTS OF:" at 11592.46,2333.71 h60
  text "X" at 11229.97,2205.08 h60
  text "ANSI IPC-A-600F CLASS ->" at 11357.96,2205.08 h60
  text "X" at 13005.97,2205.08 h60
  text "2" at 13115.96,2205.08 h60
  text "1" at 12800.96,2203.58 h60
  text "3" at 13469.96,2203.58 h60
  text "X" at 12041.97,2057.39 h60
  text "RoHS" at 12169.96,2057.39 h60
  text "OTHER" at 12814.36,2057.39 h60
  text "PER ORDER" at 13211.42,2057.39 h60
  text "ALL BOARDS MUST MEET OR EXCEED UL94-V0 REQUIREMENTS." at 10895,1903.57 h60
  text "PCB MUST BEAR THE UL94V-0 UL REGISTERED MATERIAL ID NUMBER" at 10895,1787.5 h60
  text "ADDITIONAL REQUIREMENTS:" at 10867.46,1618.08 h60
  text "MICROSECTION:" at 10942.23,1510.95 h60
  text "YES" at 11847.96,1510.95 h60
  text "REQUIRED" at 12709.46,1366.62 h60
  text "BARE BOARD ELEC. TEST:" at 10942.23,1363.76 h60
  text "NONE" at 12247.96,1363.76 h60
  text "X" at 12591.46,1363.76 h60
  text "PER ORDER" at 13301.46,1363.76 h60
  text "XX MIL VIAS REQUIRE NON-CONDUCTIVE FILL AND PLANARIZE" at 11110.38,1158.82 h59
  text "XX MIL VIAS REQUIRE CONDUCTIVE FILL AND PLANARIZE" at 11118.38,1054.84 h60
  text "OUTER XX MIL TRACES REQUIRE 50 OHM SINGLE-ENDED IMPEDANCE" at 11117.39,891.46 h58
  text "LAYER 2 & 3 (INNER LAYERS) XX MIL WIDE, XX MIL SPACE / TRACES REQUIRE 100 OHM DIFFERENTIAL IMPEDANCE" at 11109.39,655.74 h60
  text ".Layer_Name" at 111,-1094.49 h60
M11 Gerber Information:
  lines w10: -758,-1166.17 5842,-1166.17 ; -758,-962.83 5844,-962.83 ; -758,-759.5 -758,-1369.5 3247,-1369.5 5844,-1369.5 5844,-759.5 -757.5,-759.5 -757.5,-1369.5 818,-1369.5 ; 1707,-1369.5 1707,-759.5 ; 2974,-962.83 2974,-759.5 ; 3814,-962.83 3814,-759.5 ; 4436,-1376 4436,-1173.17
  text "ALL ARTWORK VIEWED FROM TOP SIDE" at -694.5,-891.67 h60
  text "BOARD #:" at 1782,-891.67 h60
  text ".PRJ_Number" at 2327.5,-891.67 h60
  text "REV:" at 3172,-891.67 h60
  text ".PCB_Rev" at 3463.5,-891.67 h60
  text "SVN REV:" at 4010,-891.67 h60
  text ".VersionControl_RevNumber" at 4516,-891.67 h60
  text "LAYER NAME =" at -694.5,-1094.49 h60
  text "TID #:" at 1782,-1095 h60
  text ".TID" at 2327.5,-1095 h60
  text "PLOT NAME =" at -694.5,-1300.34 h60
  text ".plot_File_Name" at 111,-1300.34 h60
  text "GENERATED    :" at 1784,-1300.34 h60
  text ".Print_Date" at 2653.5,-1300.34 h60
  text ".Print_Time" at 3382.5,-1300.34 h60
  text "TEXAS INSTRUMENTS" at 4647,-1300.34 h60
M12 Stackup:
  drawing of 399 lines, arcs and shapes, not listed
  text "Layer" at 6309.35,7516.5 h60
  text "Name" at 6719.26,7516.5 h60
  text "Material" at 7659,7516.5 h60
  text "Thickness" at 8518.77,7516.5 h60
  text "Constant" at 9168.6,7516.5 h60
  text "Board Layer Stack" at 9738.46,7516.5 h60
  text "Top Overlay" at 6719.26,7396.5 h60
  text "Top Solder" at 6719.26,7276.5 h60
  text "Solder Resist" at 7659,7276.5 h60
  text "0.40mil" at 8518.77,7276.5 h60
  text "3.5" at 9168.6,7276.5 h60
  text "1" at 6309.35,7156.5 h60
  text "Top Layer" at 6719.26,7156.5 h60
  text "2.80mil" at 8518.77,7156.5 h60
  text "Dielectric1" at 6719.26,7036.5 h60
  text "FR-4 High Tg" at 7659,7036.5 h60
  text "5.00mil" at 8518.77,7036.5 h60
  text "4.2" at 9168.6,7036.5 h60
  text "2" at 6309.35,6916.5 h60
  text "Signal Layer 1" at 6719.26,6916.5 h60
  text "2.80mil" at 8518.77,6916.5 h60
  text "Dielectric 2" at 6719.26,6796.5 h60
  text "FR-4 High Tg" at 7659,6796.5 h60
  text "10.00mil" at 8518.77,6796.5 h60
  text "4.2" at 9168.6,6796.5 h60
  text "3" at 6309.35,6676.5 h60
  text "Signal Layer 2" at 6719.26,6676.5 h60
  text "2.80mil" at 8518.77,6676.5 h60
  text "Dielectric 3" at 6719.26,6556.5 h60
  text "FR-4 High Tg" at 7659,6556.5 h60
  text "15.00mil" at 8518.77,6556.5 h60
  text "4.2" at 9168.6,6556.5 h60
  text "4" at 6309.35,6436.5 h60
  text "Signal Layer 3" at 6719.26,6436.5 h60
  text "2.80mil" at 8518.77,6436.5 h60
  text "Dielectric 4" at 6719.26,6316.5 h60
  text "FR-4 High Tg" at 7659,6316.5 h60
  text "10.00mil" at 8518.77,6316.5 h60
  text "4.2" at 9168.6,6316.5 h60
  text "5" at 6309.35,6196.5 h60
  text "Signal Layer 4" at 6719.26,6196.5 h60
  text "2.80mil" at 8518.77,6196.5 h60
  text "Dielectric 5" at 6719.26,6076.5 h60
  text "FR-4 High Tg" at 7659,6076.5 h60
  text "5.00mil" at 8518.77,6076.5 h60
  text "4.2" at 9168.6,6076.5 h60
  text "6" at 6309.35,5956.5 h60
  text "Bottom Layer" at 6719.26,5956.5 h60
  text "2.80mil" at 8518.77,5956.5 h60
  text "Bottom Solder" at 6719.26,5836.5 h60
  text "Solder Resist" at 7659,5836.5 h60
  text "0.40mil" at 8518.77,5836.5 h60
  text "3.5" at 9168.6,5836.5 h60
  text "Bottom Overlay" at 6719.26,5716.5 h60
  text ".Layer_Name" at 111,-1094.49 h60
M13 Component Bodies Top:
  text ".Layer_Name" at 111,-1094.49 h60
M14 Component Bodies Bottom:
  text ".Layer_Name" at 111,-1094.49 h60
M15 Courtyards Top:
  text ".Layer_Name" at 111,-1094.49 h60
M16 Courtyards Bottom:
  text ".Layer_Name" at 111,-1094.49 h60
Drill Drawing:
  circle w10: c5403.43,3800.18 r27.63
  lines w10: 5375.8,3054.26 5403.43,3026.64 5431.05,3054.26 5403.43,3081.89 5375.8,3054.26 ; 5375.8,3150.96 5431.05,3150.96 5431.05,3206.21 5375.8,3206.21 5375.8,3150.96 ; 5375.8,3275.28 5431.05,3275.28 5431.05,3330.53 5375.8,3330.53 5375.8,3275.28 ; 5375.8,3454.85 5431.05,3454.85 5403.43,3399.6 5375.8,3454.85 ; 5375.8,3537.73 5389.61,3537.73 5403.43,3523.92 5417.24,3537.73 5431.05,3537.73 5417.24,3551.54 5431.05,3565.36 5417.24,3565.36 5403.43,3579.17 5389.61,3565.36 5375.8,3565.36 5389.61,3551.54 5375.8,3537.73 ; 5375.8,3648.24 5403.43,3662.05 5431.05,3648.24 5417.24,3675.86 5431.05,3703.49 5403.43,3689.68 5375.8,3703.49 5389.61,3675.86 5375.8,3648.24 ; 5375.8,3896.88 5375.8,3910.69 5389.61,3924.5 5375.8,3938.32 5375.8,3952.13 5389.61,3952.13 5403.43,3938.32 5417.24,3952.13 5431.05,3952.13 5431.05,3938.32 5417.24,3924.5 5431.05,3910.69 5431.05,3896.88 5417.24,3896.88 5403.43,3910.69 5389.61,3896.88 5375.8,3896.88 ; 5375.8,4035.01 5389.61,4035.01 5389.61,4021.2 5417.24,4021.2 5417.24,4035.01 5431.05,4035.01 5431.05,4062.64 5417.24,4062.64 5417.24,4076.45 5389.61,4076.45 5389.61,4062.64 5375.8,4062.64 5375.8,4035.01 ; 5386.85,3162.01 5420,3162.01 5420,3195.16 5386.85,3195.16 5386.85,3162.01
  lines w12: 5325.71,2989.34 8479.8,2989.34 ; 5325.71,4108.22 8479.8,4108.22 ; 5663.57,2865.02 5663.57,4232.54 ; 5964.83,2865.02 5964.83,4232.54 ; 6554.73,2865.02 6554.73,4232.54 ; 6813.88,2865.02 6813.88,4232.54 ; 7189.03,2865.02 7189.03,4232.54 ; 7913.36,2865.02 7913.36,4232.54 ; 5325.71,2865.02 8479.8,2865.02 8479.8,4232.54 5325.71,4232.54 5325.71,2865.02
  text "Symbol" at 5400.3,4145.52 h72
  text "Count" at 5700.87,4145.52 h72
  text "Hole Size" at 6002.12,4145.52 h72
  text "Plated" at 6592.03,4145.52 h72
  text "Hole Type" at 6851.17,4145.52 h72
  text "Drill Layer Pair" at 7226.33,4145.52 h72
  text "Hole Tolerance" at 7950.66,4145.52 h72
  text "5" at 5700.87,4021.2 h60
  text "7.87mil (0.200mm)" at 6002.12,4021.2 h60
  text "PTH" at 6592.03,4021.2 h60
  text "Round" at 6851.17,4021.2 h60
  text "Top Layer - Bottom Layer" at 7226.33,4021.2 h60
  text "26" at 5700.87,3896.88 h60
  text "8.00mil (0.203mm)" at 6002.12,3896.88 h60
  text "PTH" at 6592.03,3896.88 h60
  text "Round" at 6851.17,3896.88 h60
  text "Top Layer - Bottom Layer" at 7226.33,3896.88 h60
  text "504" at 5700.87,3772.56 h60
  text "10.00mil (0.254mm)" at 6002.12,3772.56 h60
  text "PTH" at 6592.03,3772.56 h60
  text "Round" at 6851.17,3772.56 h60
  text "Top Layer - Bottom Layer" at 7226.33,3772.56 h60
  text "12" at 5700.87,3648.24 h60
  text "40.00mil (1.016mm)" at 6002.12,3648.24 h60
  text "PTH" at 6592.03,3648.24 h60
  text "Round" at 6851.17,3648.24 h60
  text "Top Layer - Bottom Layer" at 7226.33,3648.24 h60
  text "2" at 5700.87,3523.92 h60
  text "51.18mil (1.300mm)" at 6002.12,3523.92 h60
  text "PTH" at 6592.03,3523.92 h60
  text "Round" at 6851.17,3523.92 h60
  text "Top Layer - Bottom Layer" at 7226.33,3523.92 h60
  text "1" at 5700.87,3399.6 h60
  text "52.00mil (1.321mm)" at 6002.12,3399.6 h60
  text "PTH" at 6592.03,3399.6 h60
  text "Round" at 6851.17,3399.6 h60
  text "Top Layer - Bottom Layer" at 7226.33,3399.6 h60
  text "4" at 5700.87,3275.28 h60
  text "66.93mil (1.700mm)" at 6002.12,3275.28 h60
  text "PTH" at 6592.03,3275.28 h60
  text "Round" at 6851.17,3275.28 h60
  text "Top Layer - Bottom Layer" at 7226.33,3275.28 h60
  text "3" at 5700.87,3150.96 h60
  text "78.74mil (2.000mm)" at 6002.12,3150.96 h60
  text "NPTH" at 6592.03,3150.96 h60
  text "Round" at 6851.17,3150.96 h60
  text "Top Layer - Bottom Layer" at 7226.33,3150.96 h60
  text "4" at 5700.87,3026.64 h60
  text "125.98mil (3.200mm)" at 6002.12,3026.64 h60
  text "PTH" at 6592.03,3026.64 h60
  text "Round" at 6851.17,3026.64 h60
  text "Top Layer - Bottom Layer" at 7226.33,3026.64 h60
  text "561 Total" at 5700.87,2902.32 h60
  text ".Layer_Name" at 111,-1094.49 h60
M17 Embedded Cavity:
  text ".Layer_Name" at 111,-1094.49 h60
M18 Embedded Assembly:
  text ".Layer_Name" at 111,-1094.49 h60
M19 Embedded Keepout:
  text ".Layer_Name" at 111,-1094.49 h60

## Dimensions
0,0 to 0,3500 on M2 Board Dimensions
0,0 to 4000,0 on M2 Board Dimensions
-466,-636 to 534,-636 on M2 Board Dimensions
